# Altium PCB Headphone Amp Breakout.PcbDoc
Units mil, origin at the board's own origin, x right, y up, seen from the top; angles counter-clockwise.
Board outline 2800 x 2550 mil, 2 copper layers (Top Layer, Bottom Layer); 34 components, 25 nets, 87 pads, 3 vias.
Unrouted connection lines stored in the file: 2.
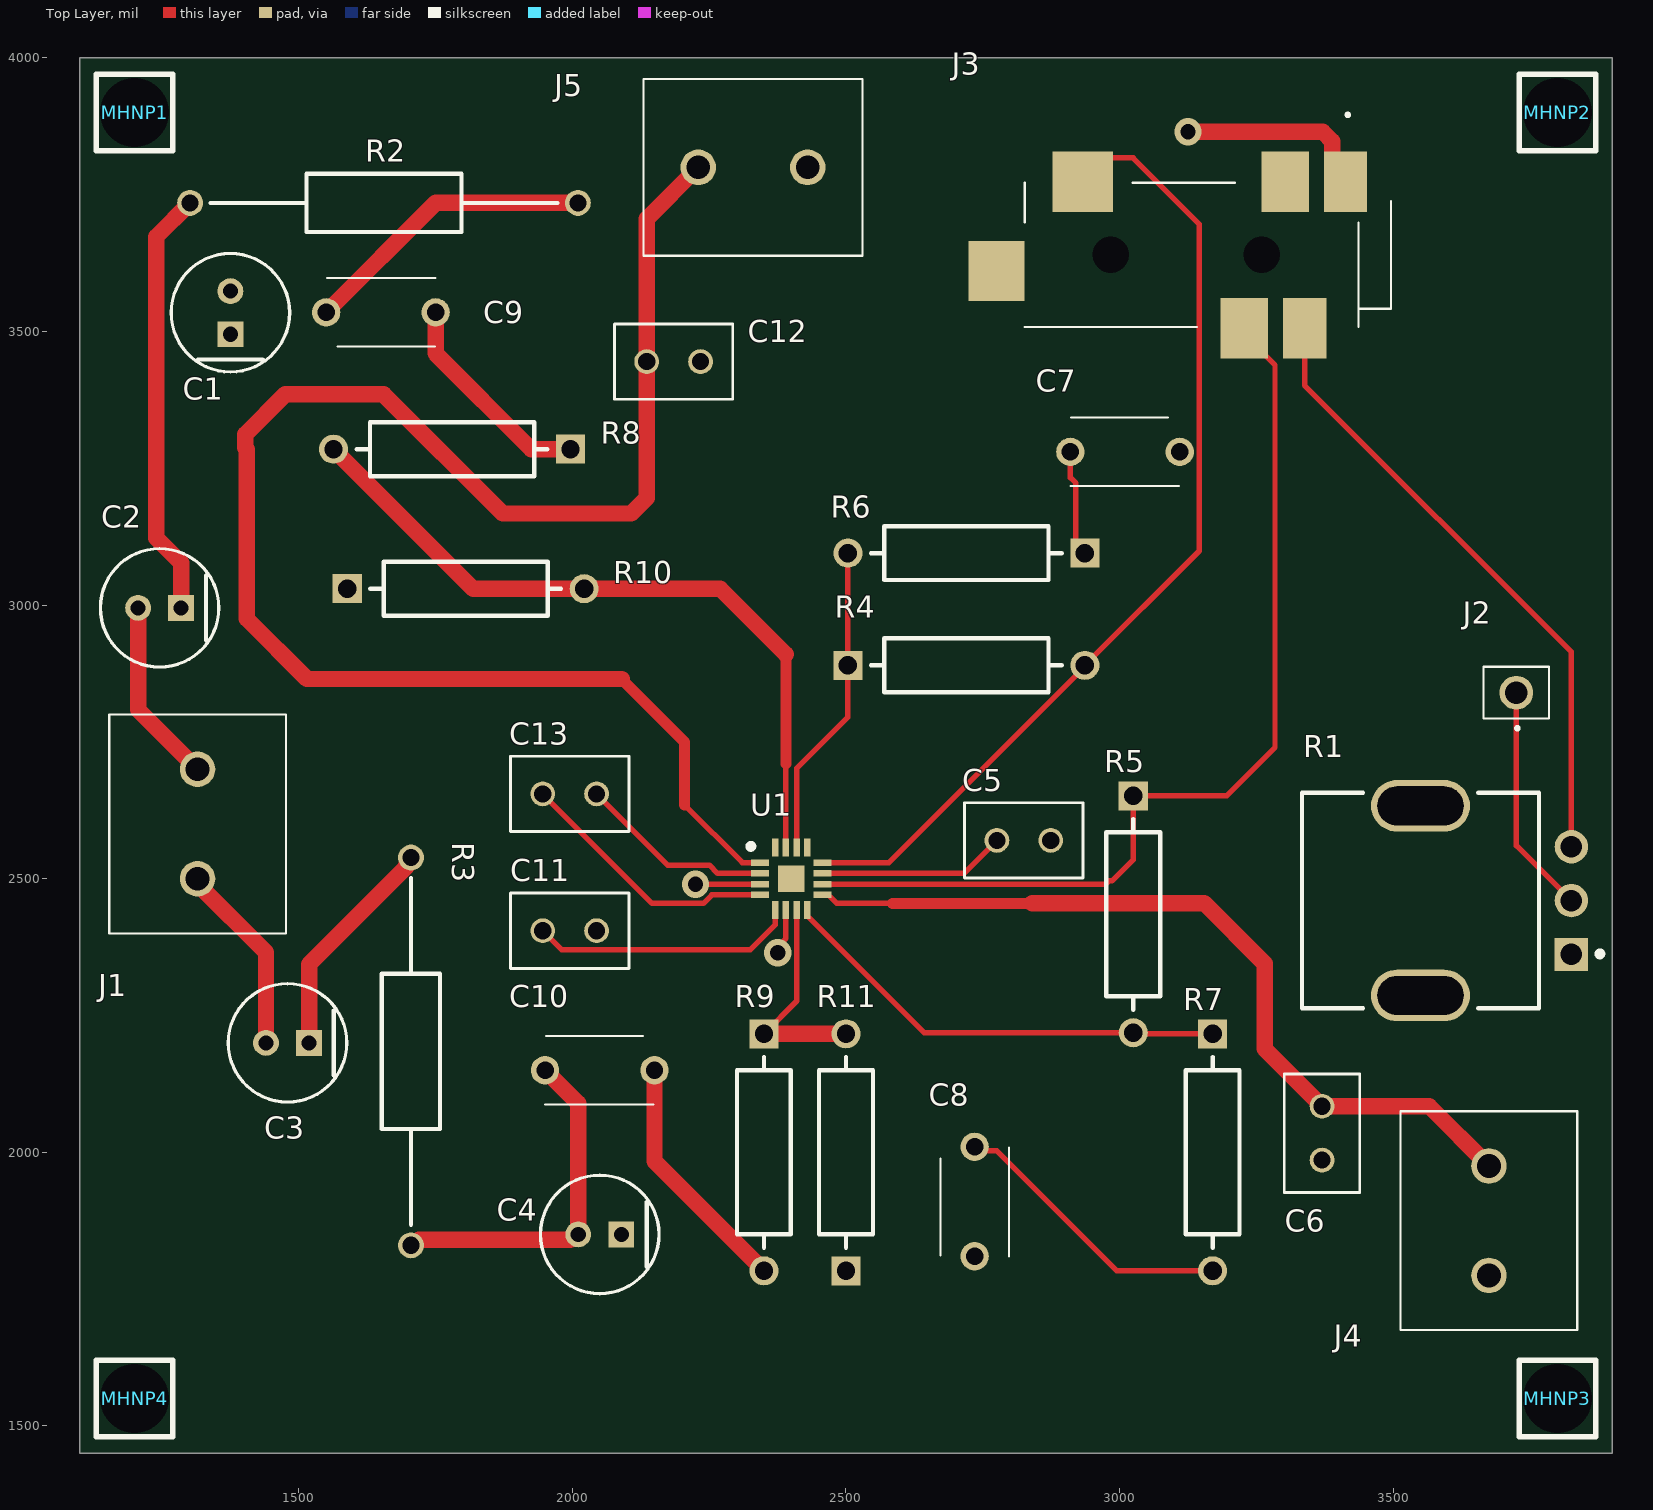
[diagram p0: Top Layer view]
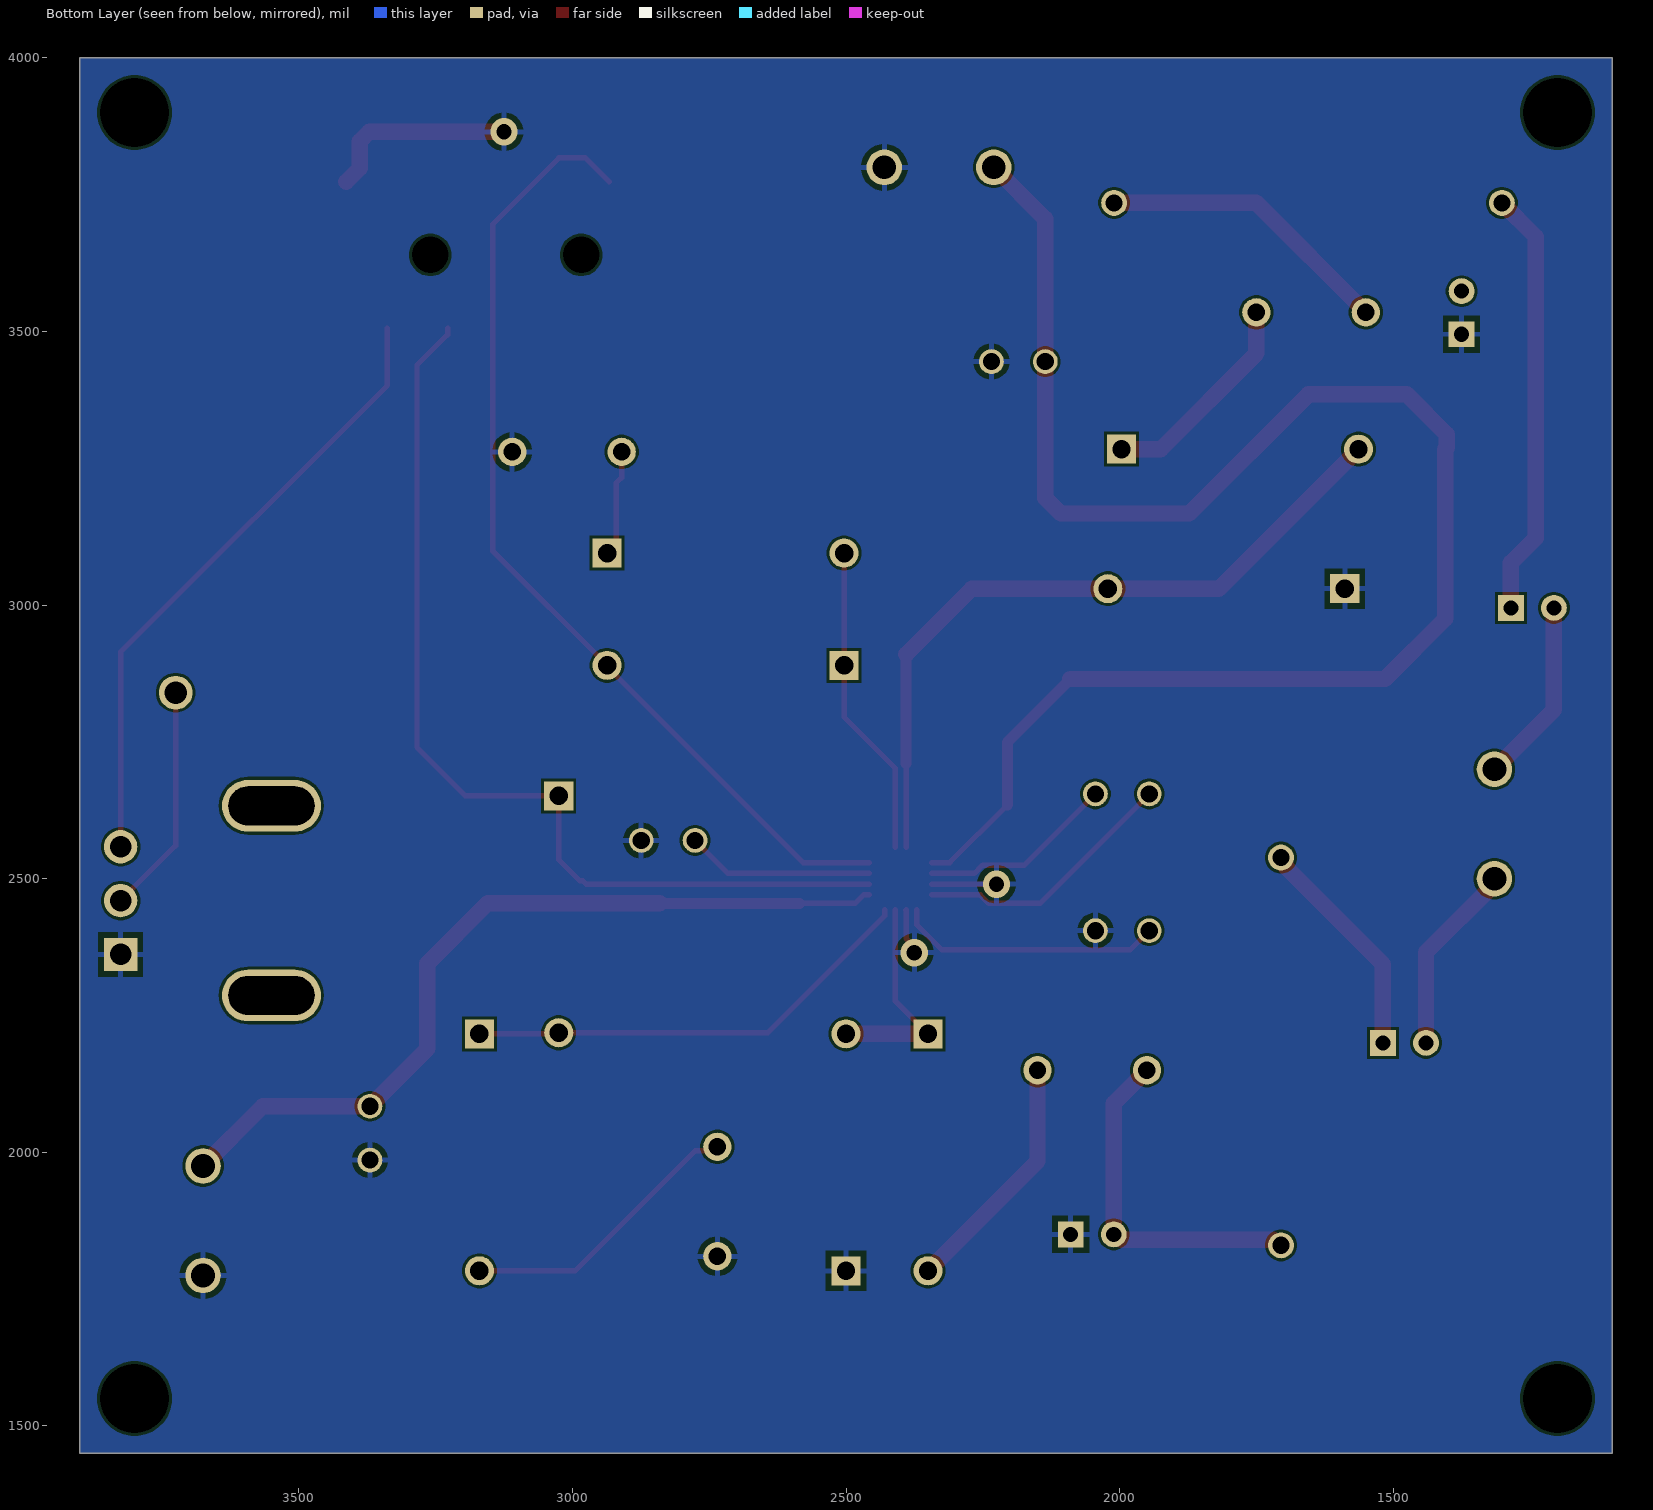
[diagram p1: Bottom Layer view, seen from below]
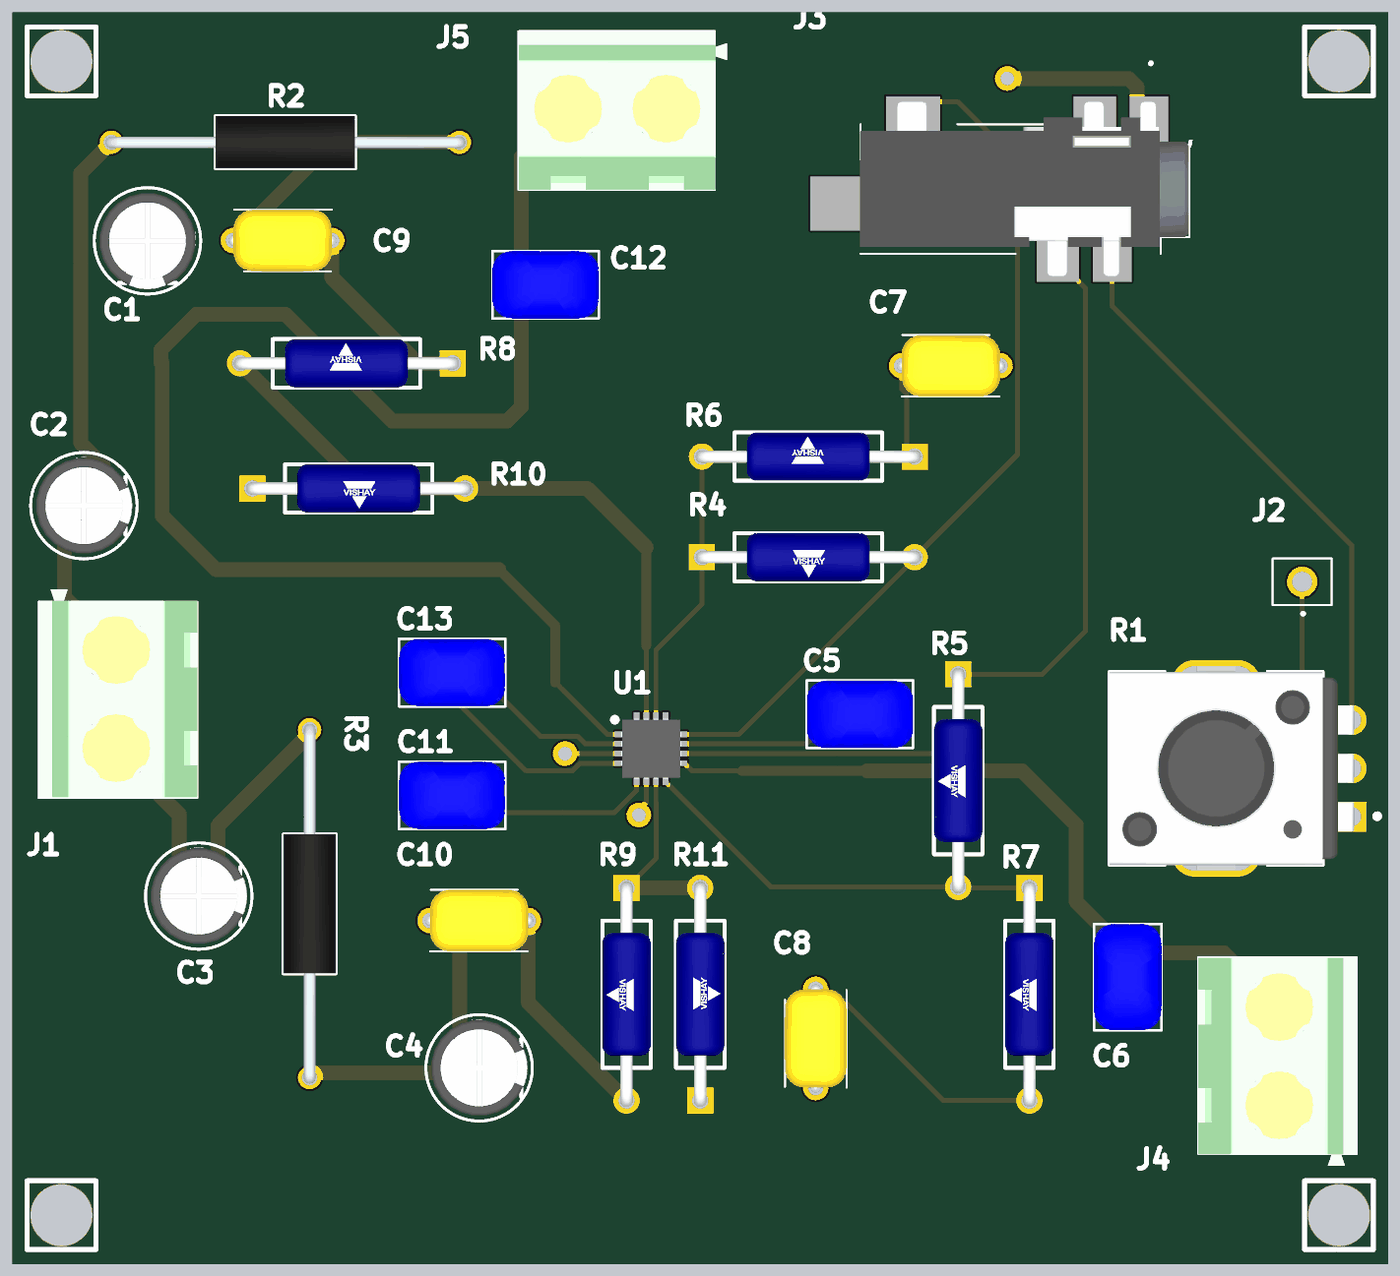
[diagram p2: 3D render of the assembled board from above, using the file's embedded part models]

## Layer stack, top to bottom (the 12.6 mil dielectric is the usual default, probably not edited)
Top Solder: solder mask 0.4, Solder Resist, Dk 3.5
Top Layer: signal copper 1.4
Dielectric 1: dielectric 12.6, FR-4, Dk 4.8
Bottom Layer: signal copper 1.4
Bottom Solder: solder mask 0.4, Solder Resist, Dk 3.5

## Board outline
1100,1450 1100,4000 3900,4000 3900,1450

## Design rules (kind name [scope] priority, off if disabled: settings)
Clearance [All] p1: gap=5 ignorepadtopadclearanceinfootprint=FALSE
PolygonConnect [All] p1: connectstyle=Relief reliefconductorwidth=10 reliefentries=4 polygonreliefangle="90 Angle" airgapwidth=10
RoutingVias [All] p1: holewidth=28 width=50 viastyle="Through Hole" minholewidth=28 minwidth=50 maxholewidth=28 maxwidth=50
SolderMaskExpansion [All] p1: expansion=4 istentingtop=FALSE
SupplyNets "Schematic Supply Nets" [InNet('GND')] p1: voltage=0.000
Width [All] p1: maxlimit=30 minlimit=10 preferedwidth=20
30 further rules are at their usual default settings.

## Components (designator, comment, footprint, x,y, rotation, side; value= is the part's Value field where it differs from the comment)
C1 "5.6µF" FP-RAD-TH-D_5_0_5-L_11_1-MFG 1375,3534.37 r90 top value=5.6uF
C2 "47uF" FP-RAD-TH-D_5_0_5-L_11_1-MFG 1245.63,2995 r180 top
C3 "47uF" FP-RAD-TH-D_5_0_5-L_11_1-MFG 1479.37,2200 r180 top
C4 "5.6µF" FP-RAD-TH-D_5_0_5-L_11_1-MFG 2050,1850 r180 top value=5.6uF
C5 "1uF" CAPRB250W50L550T350H600 2825,2570 r0 top
C6 "1uF" CAPRB250W50L550T350H600 3370,2035 r90 top
C7 "C322C474M5U5TA" C322C474M5U5TA 3110,3280 r180 top
C8 "C322C474M5U5TA" C322C474M5U5TA 2735,2010 r270 top
C9 "C322C474M5U5TA" C322C474M5U5TA 1550,3535 r0 top
C10 "C322C474M5U5TA" C322C474M5U5TA 2150,2150 r180 top
C11 "1uF" CAPRB250W50L550T350H600 1995,2405 r180 top
C12 "1uF" CAPRB250W50L550T350H600 2185,3445 r180 top
C13 "1uF" CAPRB250W50L550T350H600 1995,2655 r0 top
J1 "Power In" 2828372 1315,2500 r90 top
J2 "SSW-101-01-T-S" SSW-101-XX-YYY-S 3725,2840 r0 top
J3 "SJ-43515RS-SMT-TR" SJ43515RSSMTTR 3110,3640 r180 top
J4 "Power In" 2828372 3675,1975 r270 top
J5 "282837-2" 2828372 2230,3800 r0 top
MHNP1 "Mounting Hole Non-Plated 3.2mm" MTHNP3P2MM 1200,3900 r90 top
MHNP2 "Mounting Hole Non-Plated 3.2mm" MTHNP3P2MM 3800,3900 r90 top
MHNP3 "Mounting Hole Non-Plated 3.2mm" MTHNP3P2MM 3800,1550 r90 top
MHNP4 "Mounting Hole Non-Plated 3.2mm" MTHNP3P2MM 1200,1550 r90 top
R1 "PTV09A-4225F-B103" FP-PTV09A-4-MFG 3550,2460 r90 top
R2 "560R" RESAD1800W60L720D270 1301.34,3735 r0 top
R3 "560R" RESAD1800W60L720D270 1705,2538.66 r270 top
R4 "10k" FP-RLR07-MFG 2720,2890 r0 top
R5 "10k" FP-RLR07-MFG 3025,2435 r270 top
R6 "10k" FP-RLR07-MFG 2720,3095 r180 top
R7 "10k" FP-RLR07-MFG 3170,2000 r270 top
R8 "10k" FP-RLR07-MFG 1780,3285 r180 top
R9 "10k" FP-RLR07-MFG 2350,2000 r270 top
R10 "10k" FP-RLR07-MFG 1805,3030 r0 top
R11 "10k" FP-RLR07-MFG 2500,2000 r90 top
U1 "MAX97220AETE+" QFN50P300X300X80-17N 2400,2500 r0 top

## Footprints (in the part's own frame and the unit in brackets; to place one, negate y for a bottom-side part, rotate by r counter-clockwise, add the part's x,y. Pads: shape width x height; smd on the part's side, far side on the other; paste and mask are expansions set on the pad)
2828372 [mm]
  round 1.65 hole 1.1: 1(0,0) 2(5.08,0)
  silkscreen extent -2.54,-4.1 7.62,4.1, body extent -2.51,-4.11 8.25,4.09, height 9.84
C322C474M5U5TA [mm]
  round 1.316 hole 0.81: 1(0,0) 2(5.08,0)
  silkscreen extent 0.04,-1.59 5.08,1.59, body extent -0.25,-1.6 5.33,1.59, height 7.11
CAPRB250W50L550T350H600 [mm]
  round 1.15 hole 0.8: 1(-1.25,0) 2(1.25,0)
  silkscreen extent -2.75,-1.75 2.75,1.75, body extent -2.75,-1.75 2.75,1.75, height 3
FP-PTV09A-4-MFG [mm]
  rect 1.55x1.55 hole 1 paste-2539.97 mask+0: 1(-2.5,-7)
  round 1.55 hole 1 paste-2539.97 mask+0: 2(0,-7) 3(2.5,-7)
  rrect100% 2.4x4.6 hole 4 slot 1.8 at 0 deg paste-2539.97 mask+0: 4(-4.4,0) 5(4.4,0)
  silkscreen extent -5,-8.45 5,5.5, body extent -5.8,-7.88 5.8,5.6, height 0.25
FP-RAD-TH-D_5_0_5-L_11_1-MFG [mm]
  rect 1.2x1.2 hole 0.7 paste-2539.97 mask+0: 1(-1,0)
  round 1.2 hole 0.7 paste-2539.97 mask+0: 2(1,0)
  silkscreen extent -2.75,-2.75 2.75,2.75, body extent -2.85,-2.85 2.85,2.85, height 0.25
FP-RLR07-MFG [mm]
  rect 1.35x1.35 hole 0.85 paste-2539.97 mask+0: 1(-5.5,0)
  round 1.35 hole 0.85 paste-2539.97 mask+0: 2(5.5,0)
  silkscreen extent -4.43,-1.25 4.43,1.25, body extent -6.27,-1.35 6.27,1.35, height 0.25
MTHNP3P2MM [mm] "Mounting Hole Non-Plated 3.2mm"
  round 0 hole 3.2: ""(0,0)
  silkscreen extent -1.78,-1.78 1.78,1.78
QFN50P300X300X80-17N [mm]
  rect 0.85x0.3 smd: 1(-1.45,0.75) 2(-1.45,0.25) 3(-1.45,-0.25) 4(-1.45,-0.75) 9(1.45,-0.75) 10(1.45,-0.25) 11(1.45,0.25) 12(1.45,0.75)
  rect 0.3x0.85 smd: 5(-0.75,-1.45) 6(-0.25,-1.45) 7(0.25,-1.45) 8(0.75,-1.45) 13(0.75,1.45) 14(0.25,1.45) 15(-0.25,1.45) 16(-0.75,1.45)
  rect 1.25x1.25 smd: 17(0,0)
  silkscreen extent -2,1.38 -1.75,1.62, body extent -1.55,-1.55 1.55,1.55, height 0.8
RESAD1800W60L720D270 [mm]
  round 1.2 hole 0.8: 1(0,0) 2(18,0)
  silkscreen extent 0.95,-1.35 17.05,1.35, body extent -0.3,-1.34 18.3,1.34, height 2.7
SJ43515RSSMTTR [mm]
  rect 2x2.8 smd: 1(-7.7,-3.4) 6(-5.8,3.4)
  rect 2.8x2.8 smd: 2(4.5,-3.4)
  rect 2.2x2.8 smd: 3(-3,3.4) 4(-4.9,-3.4)
  rect 2.6x2.8 smd: 5(8.5,0.75)
  round 0.85 hole 1.7 unplated: MH1(-3.8,0) MH2(3.2,0)
  silkscreen extent -9.8,-6.55 7.2,3.35, body extent -9.96,-4.5 7.24,4.5, height 5.13
SSW-101-XX-YYY-S [mm]
  round 1.57 hole 1.04: 1(0,0)
  silkscreen extent -1.53,-1.7 1.53,1.2

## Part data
C1 C4: library part CMP-05427-001597-1, "Aluminum Electrolytic Capacitors (Radial Lead Type) AEC-Q200 Qualified 5.6uF ±20% 100V", Capacitance=5.6uF, Case/Package=Radial, ESR (Equivalent Series Resistance)=4.1R, Leakage Current=3uA, Max Operating Temperature=105°C, Min Operating Temperature=-55°C, Package Quantity=200, Ripple Current=80mA, Tolerance=20%, Voltage=100V
C2: library part CMP-05427-000413-1, "Aluminum Electrolytic Capacitors (Radial Lead Type) AEC-Q200 Qualified 47uF ±20% 35V EEUHD1V470", Case/Package=Radial, Max Operating Temperature=105°C, Min Operating Temperature=-55°C, Package Quantity=200, Ripple Current=90mA, Tolerance=20%, Voltage=35V
C3: library part CMP-05427-000413-1, "Aluminum Electrolytic Capacitors (Radial Lead Type) AEC-Q200 Qualified 47uF ±20% 35V 47uF EEUHD1V470", Case/Package=Radial, Max Operating Temperature=105°C, Min Operating Temperature=-55°C, Package Quantity=200, Ripple Current=90mA, Tolerance=20%, Voltage=35V
C5 C6 C11 C12 C13: library part CMP-030-000003-1, "1 ÂµF Â±10% 25V Ceramic Capacitor X7R Radial", Package="Radial TDK"
C7 C8 C9 C10: "Capacitor", Manufacturer_Name=KEMET, Mouser Part Number=80-C322C474M5U
J1: library part 282837-2, "Connector", Manufacturer_Name="TE Connectivity", Mouser Part Number=571-2828372
J2: "Connector", Manufacturer_Name=SAMTEC, Mouser Part Number=200-SSW10101TS
J3: library part CMP-004-000000-1, "Connector", Manufacturer_Name="Same Sky", Mouser Part Number=490-SJ43515RS-SMT-TR
J4: library part 282837-2, "Connector / 282837-2", Manufacturer_Name="TE Connectivity", Mouser Part Number=571-2828372
J5: "Connector", Manufacturer_Name="TE Connectivity", Mouser Part Number=571-2828372
MHNP1 MHNP2 MHNP3 MHNP4: library part MHNP3P2MM, "Mounting Hole Non-Plated 3.2mm drill hole"
R1: library part CMP-07234-000052-1, "POT 10K OHM 1/20W CARBON LINEAR", Max Operating Temperature=50°C, Max Power Dissipation=50mW, Min Operating Temperature=-10°C, Package Quantity=100, Resistance=10kR, Resistance Tolerance=20%, Resistor Type=Carbon
R2 R3: library part H8560RFYA, "Resistor", Manufacturer_Name="TE Connectivity", Mouser Part Number=279-H8560RFYA
R4 R5 R6 R7 R8 R9 R10 R11: library part CMP-00030-39449004-1, "RLR07C1002FSB14 Fixed Resistor, Metal Film, 0.25W, 10000ohm, 250V, 1% +/-Tol, 100ppm/Cel, Through Hole Mount", Case/Package=Conformal, Max Operating Temperature=150°C, Max Power Dissipation=250mW, Min Operating Temperature=-65°C, Resistance=10kΩ, Temperature Coefficient=100ppm/°C, Tolerance=1%, Voltage Rating=250V
U1: "Integrated Circuit", Manufacturer_Name="Analog Devices", Mouser Part Number=700-MAX97220AETE+

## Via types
v1: diameter 50, hole 28, Top Layer to Bottom Layer, 3 vias

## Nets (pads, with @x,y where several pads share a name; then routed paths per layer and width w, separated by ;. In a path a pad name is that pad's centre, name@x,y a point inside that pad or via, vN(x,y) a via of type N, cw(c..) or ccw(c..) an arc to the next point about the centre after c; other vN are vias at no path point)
GND: C1.1 C4.1 C5.2 C6.1 C7.1 C8.2 C11.1 C12.1 J3.1 J4.2 J5.2 R1.1 R10.1 R11.1 U1.3 U1.6 | length 558.2
  Top Layer w10: v1(2225,2490) 2225.08,2490.08 2342.83,2490.08 U1.3 ; v1(2375,2365) 2375,2375.82 2390.16,2390.98 U1.6 U1.6@2391.06,2442.01
  Top Layer w30: v1(3125,3865) 3371.21,3865 3388.78,3847.43 3388.78,3798.23 J3.1
NetC1_2: C1.2 C9.1 R2.2 | length 542.8
  Top Layer w30: C9.1 1750,3735 R2.2
NetC2_1: C2.1 R2.1 | length 784.6
  Top Layer w30: C2.1 1285,3077.08 1239.37,3122.71 1239.37,3673.03 R2.1
NetC2_2: C2.2 J1.2 | length 340
  Top Layer w30: C2.2 1206.26,2808.74 J1.2
NetC3_1: C3.1 R3.1 | length 415.8
  Top Layer w30: C3.1 1518.74,2343.74 1696.38,2521.38 1696.38,2525.37 1705,2534 R3.1
NetC3_2: C3.2 J1.1 | length 351.8
  Top Layer w30: J1.1 1315,2490.54 1440,2365.54 C3.2
NetC4_2: C4.2 C10.2 R3.2 | length 639
  Top Layer w30: R3.2 1709.67,1830 1719.67,1840 1995.96,1840 2005.96,1850 C4.2 2010.63,2089.37 C10.2
NetC5_1: C5.1 U1.11 | length 343.6
  Top Layer w10: U1.11 2715.63,2509.84 C5.1
NetC6_2: C6.2 J4.1 U1.9 U1.13 | length 1514.4
  Top Layer w10: U1.9 2467.91,2470.47 2483.39,2455 2585,2455
  Top Layer w20: 2585,2455 2840,2455
  Top Layer w30: 2840,2455 3155,2455 3265,2345 3265,2189.21 C6.2 3565.79,2084.21 J4.1
NetC7_2: C7.2 R6.1 | length 196
  Top Layer w10: C7.2 2910,3232.93 2920,3222.93 2920,3111.54 R6.1
NetC8_1: C8.1 R7.2 | length 528.8
  Top Layer w10: C8.1 2742.44,2002.56 2775.91,2002.56 2995,1783.46 R7.2
NetC9_2: C9.2 R8.1 | length 394
  Top Layer w30: C9.2 1750,3459.96 1924.96,3285 R8.1
NetC10_1: C10.1 R9.2 | length 449.4
  Top Layer w30: C10.1 2150,1983.46 R9.2
NetC11_2: C11.2 U1.5 | length 485.6
  Top Layer w10: C11.2 1980.93,2369.86 2324.86,2369.86 2370.47,2415.47 U1.5
NetC12_2: C12.2 J5.1 U1.1 | length 3036.8
  Top Layer w10: 2205,2635 2310.47,2529.53 U1.1
  Top Layer w20: 2090,2865 2205,2750 2205,2635
  Top Layer w30: 2090,2865 1515,2865 1405,2975 1405,3285 1402.43,3287.57 1402.43,3312.43 1475,3385 1655,3385 1872.57,3167.43 2107.43,3167.43 2135.79,3195.79 C12.2 2135.79,3705.79 J5.1
NetC13_1: C13.1 U1.4 | length 486.4
  Top Layer w10: C13.1 2145.79,2455 2239.5,2455 2254.97,2470.47 U1.4
NetC13_2: C13.2 U1.2 | length 358.8
  Top Layer w10: C13.2 2174.21,2525 2250.34,2525 2265.5,2509.84 U1.2
NetJ2_1: J2.1 R1.2 | length 421.7
  Top Layer w10: J2.1 3725,2560.59 R1.2
NetJ3_2: J3.2 R4.2 U1.12 | length 1805.6
  Top Layer w10: U1.12 2578.35,2529.53 R4.2@2937.68,2888.86 ; J3.2 2976.12,3817.14 3024.67,3817.14 3145.91,3695.91 3145.91,3099.37 2937.68,2891.14 R4.2@2937.68,2888.86 ; R4.2 R4.2@2937.68,2888.86
NetJ3_3: J3.3 R5.1 U1.10 | length 1788
  Top Layer w10: U1.10 2975.16,2490.16 2981.02,2496.02 2986.02,2496.02 3025,2535 R5.1 3195.61,2651.54 3283.98,2739.9 3283.98,3438.46 3228.11,3494.33 J3.3
NetJ3_6: J3.6 R1.3 | length 1149.5
  Top Layer w10: J3.6 3338.35,3401.65 3825.59,2914.41 R1.3
NetR4_1: R4.1 R6.2 U1.14 | length 576.7
  Top Layer w10: U1.14 2409.84,2701.56 2503.46,2795.18 R4.1 R6.2
NetR5_2: R5.2 R7.1 U1.8 | length 840.6
  Top Layer w10: U1.8 2429.53,2432.09 2643.15,2218.46 R5.2 3026.93,2216.54 R7.1
NetR8_2: R8.2 R10.2 U1.15 | length 1334.6
  Top Layer w10: U1.15 2390.16,2710.16
  Top Layer w20: 2390.16,2710.16 2390.16,2909.84
  Top Layer w30: R8.2 1818.46,3030 R10.2 2270,3030 2390,2910
NetR9_1: R9.1 R11.2 U1.7 | length 401.3
  Top Layer w10: R9.1 2410,2276.54 2410,2390.76 2409.84,2390.92 U1.7
  Top Layer w30: R9.1 R11.2
pads on no net: J3.4 J3.5 J3.MH1 J3.MH2 MHNP1. MHNP2. MHNP3. MHNP4. R1.4 R1.5 U1.16 U1.17

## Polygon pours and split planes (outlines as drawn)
GND on Bottom Layer "GND_L02_P000" (solid, pour order 0): 1100,1450 3900,1450 3900,4000 1100,4000

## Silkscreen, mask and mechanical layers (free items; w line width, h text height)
Mechanical 1:
  the board outline again, w10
